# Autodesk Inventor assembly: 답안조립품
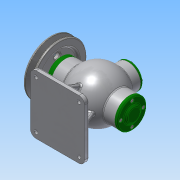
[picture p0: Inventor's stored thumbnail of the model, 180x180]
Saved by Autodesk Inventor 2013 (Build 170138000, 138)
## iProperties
Created: 2018-06
Part Number: 답안조립품
Document SubType Name: Assembly
Designer: Administrator
Author: Administrator
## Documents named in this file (19)
- C:\Users\Administrator\Desktop\480612V1016\답안조립품.iam
- C:\Users\Administrator\Desktop\480612V1016\본체.ipt
- C:\Users\Administrator\Desktop\480612V1016\V-벨트풀리.ipt
- C:\Users\Administrator\Desktop\480612V1016\너트 M8.ipt
- C:\Users\Administrator\Desktop\480612V1016\뒤커버.ipt
- C:\Users\Administrator\Desktop\480612V1016\멈춤링 15x1.ipt
- C:\Users\Administrator\Desktop\480612V1016\멈춤링 35x1.6.ipt
- 멈춤링 35x1.6.ipt
- C:\Users\Administrator\Desktop\480612V1016\베어링 6202.ipt
- 베어링 6202.ipt
- C:\Users\Administrator\Desktop\480612V1016\볼트 M4x12.ipt
- C:\Users\Administrator\Desktop\480612V1016\볼트 M4x16.ipt
- C:\Users\Administrator\Desktop\480612V1016\부시.ipt
- C:\Users\Administrator\Desktop\480612V1016\상부커버.ipt
- C:\Users\Administrator\Desktop\480612V1016\슬라이드.ipt
- C:\Users\Administrator\Desktop\480612V1016\앞커버.ipt
- C:\Users\Administrator\Desktop\480612V1016\오일 실 15 30 7.ipt
- C:\Users\Administrator\Desktop\480612V1016\키 4x4x12.ipt
- C:\Users\Administrator\Desktop\480612V1016\편심축.ipt
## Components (1 placed, 1 different names)
1. V-벨트풀리:1 — 각도:1
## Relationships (1: Angle 1)
- 각도:1 [Angle]: V-벨트풀리:1
